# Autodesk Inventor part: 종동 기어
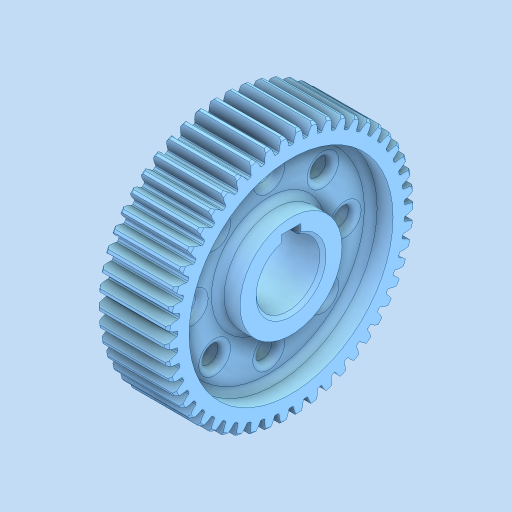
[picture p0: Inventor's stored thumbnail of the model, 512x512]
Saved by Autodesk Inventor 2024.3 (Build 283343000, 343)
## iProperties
Created: 2025-11
Part Number: 종동 기어
Material: 강철, 탄소
Document SubType Name: Modeling
Designer: PC2-03
Density: 7.85 g/cm^3
Appearance: 기본값
Author: jhkim
Sending System: Autodesk Inventor 2026
Preprocessor: ST-DEVELOPER v20.1
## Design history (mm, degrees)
feature "솔리드1"
node "솔리드2"
